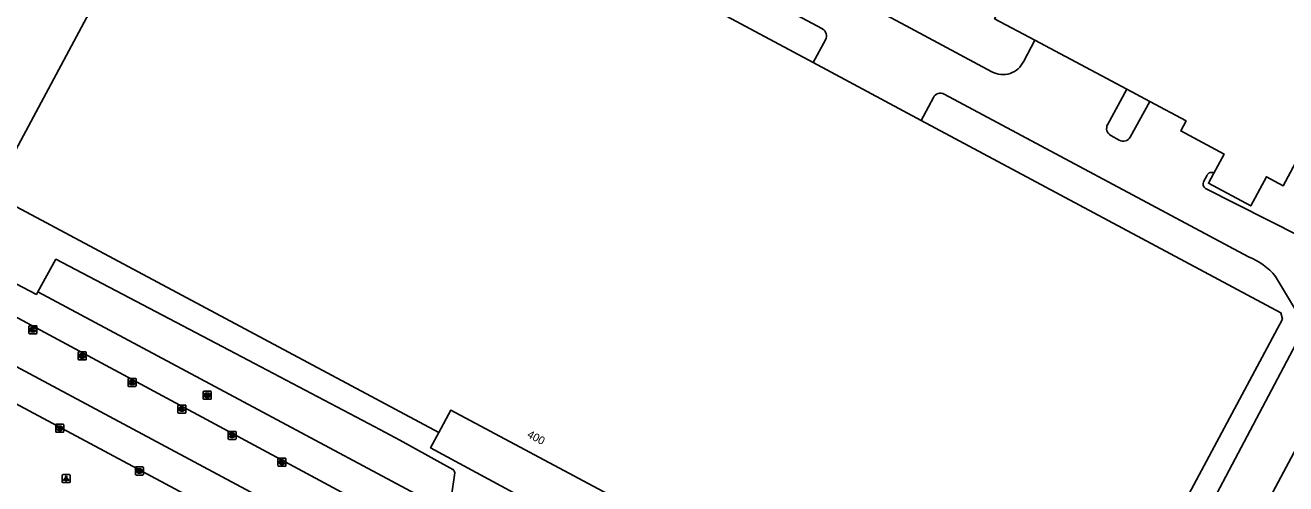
# Model space of a CAD drawing. Extents: x 159489 to 160304, y 383826 to 384530.
# Drawn here: x 159992.1 to 160149.6, y 383929.6 to 383987 of the extents above; entities that cross this region are included whole.
import ezdxf

# ---------------------------------------------------------------- set-up
doc = ezdxf.new("R2010")
doc.units = 0
for name, color, linetype in [('IMGEO_Brandkraan', 7, 'Continuous'), ('IMGEO_Kolk', 7, 'Continuous'), ('IMGEO_Lichtpunt', 7, 'Continuous'), ('IMGEO_Pand', 7, 'Continuous'), ('IMGEO_Pand_nummerreeks', 7, 'Continuous'), ('IMGEO_Pand_overbouw', 7, 'Continuous'), ('IMGEO_Rijbaan_lokaal_open', 7, 'Continuous'), ('IMGEO_Voetpad_open', 7, 'Continuous')]:
    doc.layers.add(name, color=color, linetype=linetype)

msp = doc.modelspace()

# ---------------------------------------------------------------- linework, layer by layer
at = {"layer": 'IMGEO_Brandkraan'}
for p, q in [((160014.34, 383940.27), (160014.34, 383941.12)), ((160014.42, 383941.2), (160015.27, 383941.2)), ((160015.34, 383941.12), (160015.34, 383940.27)), ((160015.27, 383940.2), (160014.42, 383940.2)), ((160014.83, 383940.98), (160014.85, 383940.98)), ((160014.85, 383940.42), (160014.83, 383940.42))]:
    msp.add_line(p, q, dxfattribs=at)
for points in [[(160014.34, 383940.27), (160014.34, 383941.12)], [(160014.42, 383941.2), (160015.27, 383941.2)], [(160015.34, 383941.12), (160015.34, 383940.27)], [(160015.27, 383940.2), (160014.42, 383940.2)], [(160014.69, 383940.9), (160014.69, 383940.5), (160014.9, 383940.5)], [(160014.92, 383940.9), (160014.69, 383940.9)], [(160014.87, 383940.82), (160014.81, 383940.82), (160014.81, 383940.74)], [(160014.81, 383940.74), (160014.87, 383940.74)], [(160014.88, 383940.66), (160014.81, 383940.66), (160014.81, 383940.58)], [(160014.81, 383940.58), (160014.88, 383940.58)]]:
    msp.add_lwpolyline(points, dxfattribs=at)
for centre, radius, start, end in [((160014.42, 383941.12), 0.0765, 91.552, 178.448), ((160014.42, 383941.12), 0.0765, 91.552, 178.448), ((160015.27, 383941.12), 0.0765, 1.552, 88.448), ((160015.27, 383941.12), 0.0765, 1.552, 88.448), ((160014.42, 383940.27), 0.0765, 181.552, 268.448), ((160014.42, 383940.27), 0.0765, 181.552, 268.448), ((160014.87, 383940.78), 0.0379, 267.8285, 90.9355), ((160014.88, 383940.62), 0.0404, 269.8759, 90.5077), ((160014.91, 383940.75), 0.251, 268.6676, 293.5347), ((160014.92, 383940.75), 0.145, 59.4692, 91.5367), ((160014.95, 383940.8), 0.0922, 285.5137, 58.1501), ((160014.95, 383940.61), 0.105, 301.3115, 78.989), ((160015.27, 383940.27), 0.0765, 271.552, 358.448), ((160015.27, 383940.27), 0.0765, 271.552, 358.448)]:
    msp.add_arc(centre, radius, start, end, dxfattribs=at)
for centre, major_axis, ratio, start_param, end_param in [((160014.83, 383940.7), (-0.387, 0.002), 0.722429, 4.712389, 7.853982), ((160014.85, 383940.7), (-0.39, 0.002), 0.717154, 1.570796, 4.712389)]:
    msp.add_ellipse(centre, major_axis=major_axis, ratio=ratio, start_param=start_param, end_param=end_param, dxfattribs=at)
at = {"layer": 'IMGEO_Kolk'}
for p, q in [((159992.57, 383948.46), (159992.57, 383949.31)), ((159992.64, 383949.39), (159993.49, 383949.39)), ((159993.05, 383949.16), (159993.08, 383949.16)), ((159993.57, 383949.31), (159993.57, 383948.46)), ((159993.49, 383948.38), (159992.64, 383948.38)), ((159993.08, 383948.61), (159993.05, 383948.61)), ((159998.72, 383945.18), (159998.72, 383946.03)), ((159998.8, 383946.11), (159999.65, 383946.11)), ((159999.21, 383945.89), (159999.23, 383945.89)), ((159999.72, 383946.03), (159999.72, 383945.18)), ((159999.65, 383945.11), (159998.8, 383945.11)), ((159999.23, 383945.33), (159999.21, 383945.33)), ((160004.97, 383941.87), (160004.97, 383942.72)), ((160005.04, 383942.8), (160005.89, 383942.8)), ((160005.97, 383942.72), (160005.97, 383941.87)), ((160005.89, 383941.79), (160005.04, 383941.79)), ((160005.45, 383942.57), (160005.48, 383942.57)), ((160005.48, 383942.02), (160005.45, 383942.02)), ((160011.26, 383939.47), (160012.12, 383939.47)), ((160011.19, 383938.54), (160011.19, 383939.4)), ((160012.12, 383938.47), (160011.26, 383938.47)), ((160011.7, 383938.69), (160011.67, 383938.69)), ((160011.68, 383939.25), (160011.7, 383939.25)), ((160012.19, 383939.4), (160012.19, 383938.54)), ((159995.93, 383936.14), (159995.93, 383936.99)), ((159996, 383937.07), (159996.85, 383937.07)), ((159996.44, 383936.29), (159996.41, 383936.29)), ((159996.42, 383936.84), (159996.44, 383936.84)), ((159996.93, 383936.99), (159996.93, 383936.14)), ((159996.85, 383936.06), (159996, 383936.06)), ((160017.46, 383935.25), (160017.46, 383936.1)), ((160017.53, 383936.18), (160018.38, 383936.18)), ((160018.38, 383935.18), (160017.53, 383935.18)), ((160017.97, 383935.4), (160017.94, 383935.4)), ((160017.95, 383935.96), (160017.97, 383935.96)), ((160018.46, 383936.1), (160018.46, 383935.25)), ((160005.88, 383930.8), (160005.88, 383931.65)), ((160005.96, 383931.73), (160006.81, 383931.73)), ((160006.88, 383931.65), (160006.88, 383930.8)), ((160023.69, 383931.89), (160023.69, 383932.74)), ((160023.76, 383932.82), (160024.62, 383932.82)), ((160024.62, 383931.82), (160023.76, 383931.82)), ((160024.2, 383932.04), (160024.17, 383932.04)), ((160024.18, 383932.6), (160024.2, 383932.6)), ((160024.69, 383932.74), (160024.69, 383931.89)), ((160006.81, 383930.72), (160005.96, 383930.72)), ((160006.37, 383931.5), (160006.4, 383931.5)), ((160006.39, 383930.95), (160006.37, 383930.95))]:
    msp.add_line(p, q, dxfattribs=at)
for points in [[(159992.57, 383948.46), (159992.57, 383949.31)], [(159992.64, 383949.39), (159993.49, 383949.39)], [(159992.89, 383949.08), (159993.01, 383949.08), (159993.01, 383948.93), (159993.14, 383949.08), (159993.3, 383949.08), (159993.16, 383948.93), (159993.31, 383948.68), (159993.16, 383948.68), (159993.07, 383948.85), (159993.01, 383948.78), (159993.01, 383948.68), (159992.89, 383948.68), (159992.89, 383949.08)], [(159993.57, 383949.31), (159993.57, 383948.46)], [(159993.49, 383948.38), (159992.64, 383948.38)], [(159998.72, 383945.18), (159998.72, 383946.03)], [(159998.8, 383946.11), (159999.65, 383946.11)], [(159999.04, 383945.81), (159999.17, 383945.81), (159999.17, 383945.66), (159999.29, 383945.81), (159999.46, 383945.81), (159999.31, 383945.66), (159999.47, 383945.41), (159999.31, 383945.41), (159999.23, 383945.57), (159999.17, 383945.5), (159999.17, 383945.41), (159999.04, 383945.41), (159999.04, 383945.81)], [(159999.72, 383946.03), (159999.72, 383945.18)], [(159999.65, 383945.11), (159998.8, 383945.11)], [(160004.97, 383941.87), (160004.97, 383942.72)], [(160005.04, 383942.8), (160005.89, 383942.8)], [(160005.97, 383942.72), (160005.97, 383941.87)], [(160005.89, 383941.79), (160005.04, 383941.79)], [(160005.29, 383942.49), (160005.41, 383942.49), (160005.41, 383942.34), (160005.54, 383942.49), (160005.7, 383942.49), (160005.56, 383942.34), (160005.71, 383942.09), (160005.56, 383942.09), (160005.47, 383942.26), (160005.41, 383942.19), (160005.41, 383942.09), (160005.29, 383942.09), (160005.29, 383942.49)], [(160011.26, 383939.47), (160012.12, 383939.47)], [(160011.19, 383938.54), (160011.19, 383939.4)], [(160012.12, 383938.47), (160011.26, 383938.47)], [(160011.51, 383939.17), (160011.63, 383939.17), (160011.63, 383939.02), (160011.76, 383939.17), (160011.93, 383939.17), (160011.78, 383939.02), (160011.93, 383938.77), (160011.78, 383938.77), (160011.7, 383938.93), (160011.63, 383938.87), (160011.63, 383938.77), (160011.51, 383938.77), (160011.51, 383939.17)], [(160012.19, 383939.4), (160012.19, 383938.54)], [(159995.93, 383936.14), (159995.93, 383936.99)], [(159996, 383937.07), (159996.85, 383937.07)], [(159996.25, 383936.76), (159996.37, 383936.76), (159996.37, 383936.61), (159996.5, 383936.76), (159996.67, 383936.76), (159996.52, 383936.61), (159996.67, 383936.36), (159996.52, 383936.36), (159996.44, 383936.53), (159996.37, 383936.46), (159996.37, 383936.36), (159996.25, 383936.36), (159996.25, 383936.76)], [(159996.93, 383936.99), (159996.93, 383936.14)], [(159996.85, 383936.06), (159996, 383936.06)], [(160017.46, 383935.25), (160017.46, 383936.1)], [(160017.53, 383936.18), (160018.38, 383936.18)], [(160018.38, 383935.18), (160017.53, 383935.18)], [(160017.78, 383935.88), (160017.9, 383935.88), (160017.9, 383935.72), (160018.03, 383935.88), (160018.2, 383935.88), (160018.05, 383935.73), (160018.2, 383935.48), (160018.05, 383935.48), (160017.97, 383935.64), (160017.9, 383935.57), (160017.9, 383935.48), (160017.78, 383935.48), (160017.78, 383935.88)], [(160018.46, 383936.1), (160018.46, 383935.25)], [(160005.88, 383930.8), (160005.88, 383931.65)], [(160005.96, 383931.73), (160006.81, 383931.73)], [(160006.88, 383931.65), (160006.88, 383930.8)], [(160023.69, 383931.89), (160023.69, 383932.74)], [(160023.76, 383932.82), (160024.62, 383932.82)], [(160024.62, 383931.82), (160023.76, 383931.82)], [(160024.01, 383932.52), (160024.13, 383932.52), (160024.13, 383932.37), (160024.26, 383932.52), (160024.43, 383932.52), (160024.28, 383932.37), (160024.43, 383932.12), (160024.28, 383932.12), (160024.2, 383932.28), (160024.13, 383932.22), (160024.13, 383932.12), (160024.01, 383932.12), (160024.01, 383932.52)], [(160024.69, 383932.74), (160024.69, 383931.89)], [(160006.81, 383930.72), (160005.96, 383930.72)], [(160006.2, 383931.42), (160006.33, 383931.42), (160006.33, 383931.27), (160006.46, 383931.42), (160006.62, 383931.42), (160006.48, 383931.27), (160006.63, 383931.02), (160006.48, 383931.02), (160006.39, 383931.19), (160006.33, 383931.12), (160006.33, 383931.02), (160006.2, 383931.02), (160006.2, 383931.42)]]:
    msp.add_lwpolyline(points, dxfattribs=at)
for centre, start, end in [((159992.64, 383949.31), 91.552, 178.448), ((159992.64, 383949.31), 91.552, 178.448), ((159993.49, 383949.31), 1.552, 88.448), ((159993.49, 383949.31), 1.552, 88.448), ((159992.64, 383948.46), 181.552, 268.448), ((159992.64, 383948.46), 181.552, 268.448), ((159993.49, 383948.46), 271.552, 358.448), ((159993.49, 383948.46), 271.552, 358.448), ((159998.8, 383946.03), 91.552, 178.448), ((159998.8, 383946.03), 91.552, 178.448), ((159999.65, 383946.03), 1.552, 88.448), ((159999.65, 383946.03), 1.552, 88.448), ((159998.8, 383945.18), 181.552, 268.448), ((159998.8, 383945.18), 181.552, 268.448), ((159999.65, 383945.18), 271.552, 358.448), ((159999.65, 383945.18), 271.552, 358.448), ((160005.04, 383942.72), 91.552, 178.448), ((160005.04, 383942.72), 91.552, 178.448), ((160005.89, 383942.72), 1.552, 88.448), ((160005.89, 383942.72), 1.552, 88.448), ((160005.04, 383941.87), 181.552, 268.448), ((160005.04, 383941.87), 181.552, 268.448), ((160005.89, 383941.87), 271.552, 358.448), ((160005.89, 383941.87), 271.552, 358.448), ((160011.27, 383939.39), 91.552, 178.448), ((160011.27, 383939.39), 91.552, 178.448), ((160012.11, 383939.39), 1.552, 88.448), ((160012.11, 383939.39), 1.552, 88.448), ((160011.27, 383938.54), 181.552, 268.448), ((160011.27, 383938.54), 181.552, 268.448), ((160012.11, 383938.54), 271.552, 358.448), ((160012.11, 383938.54), 271.552, 358.448), ((159996, 383936.99), 91.552, 178.448), ((159996, 383936.99), 91.552, 178.448), ((159996.85, 383936.99), 1.552, 88.448), ((159996.85, 383936.99), 1.552, 88.448), ((159996, 383936.14), 181.552, 268.448), ((159996, 383936.14), 181.552, 268.448), ((159996.85, 383936.14), 271.552, 358.448), ((159996.85, 383936.14), 271.552, 358.448), ((160017.53, 383936.1), 91.552, 178.448), ((160017.53, 383936.1), 91.552, 178.448), ((160017.53, 383935.25), 181.552, 268.448), ((160017.53, 383935.25), 181.552, 268.448), ((160018.38, 383936.1), 1.552, 88.448), ((160018.38, 383936.1), 1.552, 88.448), ((160018.38, 383935.25), 271.552, 358.448), ((160018.38, 383935.25), 271.552, 358.448), ((160005.96, 383931.65), 91.552, 178.448), ((160005.96, 383931.65), 91.552, 178.448), ((160006.81, 383931.65), 1.552, 88.448), ((160006.81, 383931.65), 1.552, 88.448), ((160023.76, 383932.74), 91.552, 178.448), ((160023.76, 383932.74), 91.552, 178.448), ((160023.76, 383931.89), 181.552, 268.448), ((160023.76, 383931.89), 181.552, 268.448), ((160024.61, 383932.74), 1.552, 88.448), ((160024.61, 383932.74), 1.552, 88.448), ((160024.61, 383931.89), 271.552, 358.448), ((160024.61, 383931.89), 271.552, 358.448), ((160005.96, 383930.8), 181.552, 268.448), ((160005.96, 383930.8), 181.552, 268.448), ((160006.81, 383930.8), 271.552, 358.448), ((160006.81, 383930.8), 271.552, 358.448)]:
    msp.add_arc(centre, 0.0765, start, end, dxfattribs=at)
for centre, major_axis, ratio, start_param, end_param in [((159993.05, 383948.88), (-0.387, 0.002), 0.722429, 4.712389, 7.853982), ((159993.08, 383948.88), (-0.39, 0.002), 0.717154, 1.570796, 4.712389), ((159999.21, 383945.61), (-0.387, 0.002), 0.722429, 4.712389, 7.853982), ((159999.23, 383945.61), (-0.39, 0.002), 0.717154, 1.570796, 4.712389), ((160005.45, 383942.29), (-0.387, 0.002), 0.722429, 4.712389, 7.853982), ((160005.48, 383942.29), (-0.39, 0.002), 0.717154, 1.570796, 4.712389), ((160011.68, 383938.97), (-0.387, 0.002), 0.722429, 4.712389, 7.853982), ((160011.7, 383938.97), (-0.39, 0.002), 0.717154, 1.570796, 4.712389), ((159996.41, 383936.56), (-0.387, 0.002), 0.722429, 4.712389, 7.853982), ((159996.44, 383936.56), (-0.39, 0.002), 0.717154, 1.570796, 4.712389), ((160017.94, 383935.68), (-0.387, 0.002), 0.722429, 4.712389, 7.853982), ((160017.97, 383935.68), (-0.39, 0.002), 0.717154, 1.570796, 4.712389), ((160024.18, 383932.32), (-0.387, 0.002), 0.722429, 4.712389, 7.853982), ((160024.2, 383932.32), (-0.39, 0.002), 0.717154, 1.570796, 4.712389), ((160006.37, 383931.22), (-0.387, 0.002), 0.722429, 4.712389, 7.853982), ((160006.39, 383931.22), (-0.39, 0.002), 0.717154, 1.570796, 4.712389)]:
    msp.add_ellipse(centre, major_axis=major_axis, ratio=ratio, start_param=start_param, end_param=end_param, dxfattribs=at)
at = {"layer": 'IMGEO_Lichtpunt'}
for p, q in [((159996.73, 383930.67), (159996.73, 383929.87)), ((159996.73, 383930.67), (159996.73, 383929.87)), ((159997.63, 383930.77), (159996.82, 383930.77)), ((159997.63, 383930.77), (159996.82, 383930.77)), ((159997.72, 383929.87), (159997.72, 383930.67)), ((159997.72, 383929.87), (159997.72, 383930.67)), ((159996.82, 383929.77), (159997.63, 383929.77)), ((159996.82, 383929.77), (159997.63, 383929.77))]:
    msp.add_line(p, q, dxfattribs=at)
for points in [[(159997.1, 383930.34), (159997.14, 383930.31), (159996.95, 383930.05), (159996.91, 383930.08), (159997.1, 383930.34)], [(159997.2, 383930.29), (159997.25, 383930.29), (159997.25, 383929.97), (159997.2, 383929.97), (159997.2, 383930.29)], [(159997.31, 383930.31), (159997.35, 383930.34), (159997.54, 383930.07), (159997.5, 383930.05), (159997.31, 383930.31)]]:
    msp.add_lwpolyline(points, dxfattribs=at)
msp.add_circle((159997.23, 383930.47), 0.0994, dxfattribs=at)
for centre, start, end in [((159996.82, 383930.67), 90, 180), ((159996.82, 383930.67), 90, 180), ((159997.63, 383930.67), 0, 90), ((159997.63, 383930.67), 0, 90), ((159996.82, 383929.87), 180, 270), ((159996.82, 383929.87), 180, 270), ((159997.63, 383929.87), 270, 0), ((159997.63, 383929.87), 270, 360)]:
    msp.add_arc(centre, 0.0946, start, end, dxfattribs=at)
at = {"layer": 'IMGEO_Pand'}
for points in [[(160118.27, 383985.09), (160113.25, 383987.77), (160133.95, 384026.36)], [(160090.59, 383982.28), (160018.18, 384021.04), (160017.35, 384020.78), (160016.31, 384018.83)], [(159989.33, 383968.4), (160002.95, 383993.83), (160003.94, 383993.3), (160011.18, 384006.86), (160010.58, 384007.18), (160010.48, 384006.98), (160010.09, 384007.19), (160010.19, 384007.39), (160009.52, 384007.74)], [(160170.75, 384006.97), (160168.71, 384003.16), (160167.74, 384003.68), (160166.14, 384000.69), (160167.11, 384000.17), (160149.32, 383966.89), (160147.2, 383968.02), (160145.25, 383964.37), (160139.96, 383967.19), (160140.64, 383968.48)], [(160129.76, 383978.95), (160118.27, 383985.09)], [(160090.59, 383982.28), (160104.06, 383975.06)], [(160132.63, 383977.41), (160129.76, 383978.95)], [(160140.64, 383968.48), (160141.91, 383970.85), (160136.51, 383973.74), (160137.17, 383974.99), (160132.63, 383977.41)], [(159989.33, 383968.4), (159988.3, 383966.46), (159988.49, 383965.57), (159995.29, 383961.94), (160043.8, 383936.05), (160045.31, 383938.84), (160065.57, 383928.01), (160064.04, 383925.22), (160112.85, 383899.1), (160119.34, 383895.63), (160120.16, 383895.88), (160149.23, 383950.19), (160149, 383951.01), (160104.06, 383975.06)]]:
    msp.add_lwpolyline(points, dxfattribs=at)
at = {"layer": 'IMGEO_Pand_overbouw'}
msp.add_lwpolyline([(160045.31, 383938.84), (160043.8, 383936.05), (160042.76, 383934.13), (160062.95, 383923.21), (160064.04, 383925.22), (160065.57, 383928.01)], close=True, dxfattribs=at)
at = {"layer": 'IMGEO_Rijbaan_lokaal_open'}
for points in [[(160051.05, 384008.29), (160054.05, 384006.68), (160056.2, 384002.21), (160060.32, 384000), (160066.87, 383996.49), (160071, 383997.6), (160091.72, 383986.49)], [(160112.89, 383981.13), (160102.73, 383986.6), (160101.57, 383987.22), (160080.06, 383998.71), (160080.04, 383998.72)], [(160092.13, 383985.14), (160090.59, 383982.28)], [(160118.27, 383985.09), (160116.88, 383982.46)], [(160127.36, 383974.52), (160129.76, 383978.95)], [(160104.06, 383975.06), (160105.59, 383977.92)], [(160106.95, 383978.33), (160144.98, 383957.98)], [(160132.63, 383977.41), (160130.19, 383972.97)], [(160128.82, 383972.58), (160127.75, 383973.17)], [(160139.36, 383967.36), (160139.81, 383968.23)], [(159993.67, 383953.62), (159993.5, 383953.31), (159981.38, 383959.62), (159983.84, 383964.06), (159985.87, 383967.7)], [(160151.4, 383960.58), (160139.61, 383966.55)], [(159978.66, 383957.07), (160037.66, 383925.31)], [(160148.35, 383955.56), (160151.23, 383950.76), (160151.52, 383950.04), (160151.63, 383949.27), (160151.55, 383948.5), (160151.28, 383947.77), (160136.85, 383920.54)], [(160045.07, 383926.11), (159993.67, 383953.62)], [(160033.77, 383921.35), (159974.43, 383953.14)], [(159972.63, 383949.42), (160029.55, 383918.93)], [(160142.15, 383917.59), (160153.27, 383938.4), (160158.15, 383947.47), (160189.76, 383930.48), (160189.33, 383929.35), (160183.8, 383919.1)]]:
    msp.add_lwpolyline(points, dxfattribs=at)
for centre, radius, start, end in [((160091.24, 383985.61), 1, 331.942, 61.6196), ((160114.27, 383983.66), 2.87, 241.5088, 335.318), ((160106.47, 383977.45), 0.999, 61.8678, 151.8725), ((160128.24, 383974.05), 0.998, 151.3891, 241.0498), ((160129.31, 383973.45), 1, 240.8038, 331.2645), ((160140.34, 383967.96), 0.601, 59.928, 152.4341), ((160139.89, 383967.08), 0.599, 152.4915, 241.9735), ((160141.95, 383950.2), 8.35, 39.9323, 68.7229)]:
    msp.add_arc(centre, radius, start, end, dxfattribs=at)
at = {"layer": 'IMGEO_Voetpad_open'}
for points in [[(160045.53, 383931.43), (160040.49, 383934.22), (160038.9, 383935.08), (160035.8, 383936.73), (160017.6, 383946.32), (159995.94, 383957.7), (159993.67, 383953.62)], [(160045.07, 383926.11), (160045.78, 383930.98)]]:
    msp.add_lwpolyline(points, dxfattribs=at)
msp.add_arc((160045.21, 383930.96), 0.574, 1.8948, 55.6785, dxfattribs=at)

# ---------------------------------------------------------------- texts
at = {"layer": 'IMGEO_Pand_nummerreeks'}
msp.add_text('400', height=1, rotation=331.8735, dxfattribs=at).set_placement((160054.74, 383935.5))

doc.saveas('drawing.dxf')
